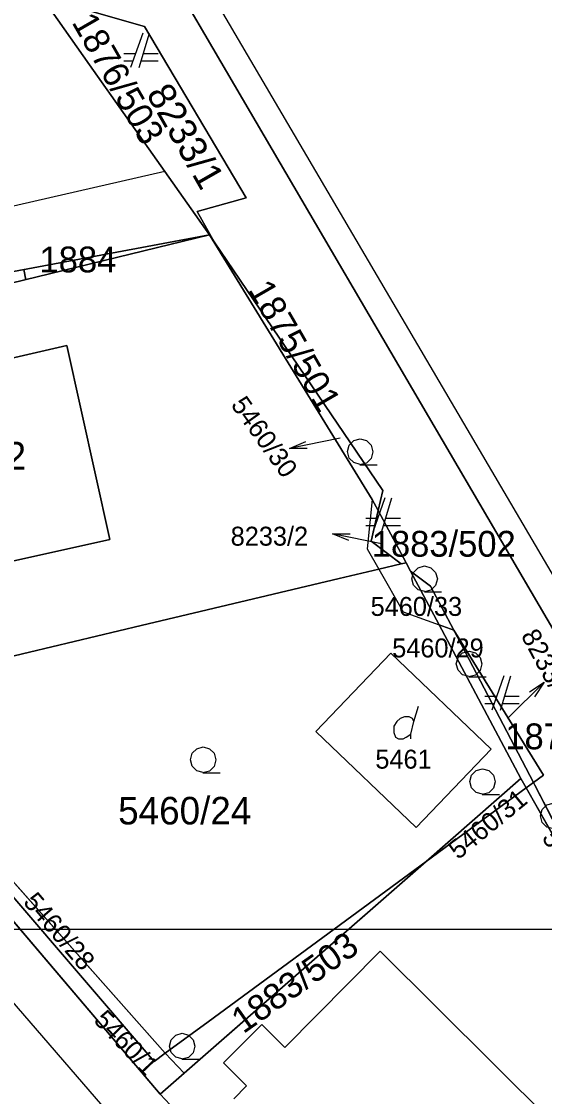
# Model space of a CAD drawing. Extents: x -263587 to -261993, y -1238795 to -1236748.
# Drawn here: x -262882.4 to -262852, y -1237097.8 to -1237035.4 of the extents above; entities that cross this region are included whole.
import ezdxf

# ---------------------------------------------------------------- set-up
doc = ezdxf.new("R2010")
doc.units = 0
for name, color, linetype in [('Vrstva 1', 7, 'Continuous'), ('Vrstva 3', 7, 'Continuous'), ('Vrstva 51', 7, 'Continuous')]:
    doc.layers.add(name, color=color, linetype=linetype)

msp = doc.modelspace()

# ---------------------------------------------------------------- linework, layer by layer
at = {"layer": 'Vrstva 1'}
for p, q in [((-262873.84, -1237029.6), (-262829.31, -1237105.43)), ((-262833.86, -1237100.89), (-262873.83, -1237032.62)), ((-262873.83, -1237032.62), (-262833.86, -1237100.89)), ((-262875.29, -1237035.67), (-262880.65, -1237034.14)), ((-262880.65, -1237034.14), (-262875.29, -1237035.67)), ((-262878.48, -1237037.88), (-262881.06, -1237034.23)), ((-262881.06, -1237034.23), (-262878.48, -1237037.88)), ((-262875.39, -1237036.05), (-262876.09, -1237038.05)), ((-262875.59, -1237038.05), (-262874.99, -1237036.05)), ((-262869.38, -1237045.62), (-262875.29, -1237035.67)), ((-262875.29, -1237035.67), (-262869.38, -1237045.62)), ((-262875.81, -1237037.25), (-262876.49, -1237037.25)), ((-262874.49, -1237037.25), (-262875.35, -1237037.25)), ((-262874.1, -1237044.08), (-262878.48, -1237037.88)), ((-262878.48, -1237037.88), (-262874.1, -1237044.08)), ((-262876.49, -1237037.65), (-262875.95, -1237037.65)), ((-262875.47, -1237037.65), (-262874.49, -1237037.65)), ((-262874.1, -1237044.08), (-262883.33, -1237046.2)), ((-262871.5, -1237047.76), (-262874.1, -1237044.08)), ((-262874.1, -1237044.08), (-262871.5, -1237047.76)), ((-262872.23, -1237046.4), (-262869.38, -1237045.62)), ((-262869.38, -1237045.62), (-262872.23, -1237046.4)), ((-262871.23, -1237048.16), (-262872.23, -1237046.4)), ((-262872.23, -1237046.4), (-262871.23, -1237048.16)), ((-262871.5, -1237047.76), (-262911.11, -1237057.42)), ((-262911.11, -1237057.42), (-262871.5, -1237047.76)), ((-262909.25, -1237054.82), (-262871.5, -1237047.76)), ((-262871.5, -1237047.76), (-262909.25, -1237054.82)), ((-262862.05, -1237063.12), (-262871.5, -1237047.76)), ((-262871.5, -1237047.76), (-262871.23, -1237048.16)), ((-262871.23, -1237048.16), (-262871.5, -1237047.76)), ((-262871.5, -1237047.76), (-262862.05, -1237063.12)), ((-262861.43, -1237062.6), (-262871.23, -1237048.16)), ((-262871.23, -1237048.16), (-262861.43, -1237062.6)), ((-262891.59, -1237056.9), (-262879.8, -1237054.19)), ((-262879.8, -1237054.19), (-262891.59, -1237056.9)), ((-262879.8, -1237054.19), (-262877.29, -1237065.45)), ((-262877.29, -1237065.45), (-262879.8, -1237054.19)), ((-262865.838, -1237060.161), (-262866.858, -1237060.168)), ((-262861.7, -1237063.77), (-262861.43, -1237062.6)), ((-262861.43, -1237062.6), (-262861.7, -1237063.77)), ((-262862.05, -1237063.12), (-262862.34, -1237066)), ((-262861.7, -1237063.77), (-262862.05, -1237063.12)), ((-262862.05, -1237063.12), (-262861.7, -1237063.77)), ((-262861.32, -1237063.03), (-262862.02, -1237065.03)), ((-262861.52, -1237065.03), (-262860.92, -1237063.03)), ((-262862.12, -1237065.55), (-262861.7, -1237063.77)), ((-262861.7, -1237063.77), (-262862.12, -1237065.55)), ((-262860.09, -1237066.8), (-262861.7, -1237063.77)), ((-262861.7, -1237063.77), (-262860.09, -1237066.8)), ((-262861.74, -1237064.23), (-262862.42, -1237064.23)), ((-262862.42, -1237064.63), (-262861.88, -1237064.63)), ((-262861.4, -1237064.63), (-262860.42, -1237064.63)), ((-262860.42, -1237064.23), (-262861.28, -1237064.23)), ((-262863.42, -1237065.519), (-262864.36, -1237065.125)), ((-262877.29, -1237065.45), (-262889.03, -1237068.06)), ((-262889.03, -1237068.06), (-262877.29, -1237065.45)), ((-262862.34, -1237066), (-262861.67, -1237067.17)), ((-262860.38, -1237066.87), (-262862.12, -1237065.55)), ((-262862.12, -1237065.55), (-262860.38, -1237066.87)), ((-262861.67, -1237067.17), (-262863.97, -1237067.72)), ((-262863.97, -1237067.72), (-262861.67, -1237067.17)), ((-262860.38, -1237066.87), (-262861.67, -1237067.17)), ((-262861.67, -1237067.17), (-262860.38, -1237066.87)), ((-262861.67, -1237067.17), (-262860.25, -1237069.65)), ((-262860.09, -1237066.8), (-262860.38, -1237066.87)), ((-262860.38, -1237066.87), (-262860.09, -1237066.8)), ((-262859.83, -1237067.29), (-262860.09, -1237066.8)), ((-262860.09, -1237066.8), (-262859.83, -1237067.29)), ((-262858.66, -1237068.17), (-262859.83, -1237067.29)), ((-262858.17, -1237070.41), (-262859.83, -1237067.29)), ((-262859.83, -1237067.29), (-262858.66, -1237068.17)), ((-262859.83, -1237067.29), (-262858.17, -1237070.41)), ((-262863.97, -1237067.72), (-262875.47, -1237070.45)), ((-262875.47, -1237070.45), (-262863.97, -1237067.72)), ((-262857.32, -1237070.72), (-262858.66, -1237068.17)), ((-262858.66, -1237068.17), (-262857.32, -1237070.72)), ((-262860.25, -1237069.65), (-262858.17, -1237070.41)), ((-262857.32, -1237070.72), (-262858.17, -1237070.41)), ((-262853.42, -1237079.33), (-262858.17, -1237070.41)), ((-262858.17, -1237070.41), (-262857.32, -1237070.72)), ((-262858.17, -1237070.41), (-262853.42, -1237079.33)), ((-262875.47, -1237070.45), (-262881.96, -1237071.99)), ((-262881.96, -1237071.99), (-262875.47, -1237070.45)), ((-262852.1, -1237079.13), (-262857.32, -1237070.72)), ((-262857.32, -1237070.72), (-262852.1, -1237079.13)), ((-262852.68, -1237079.56), (-262857.32, -1237070.72)), ((-262857.32, -1237070.72), (-262852.68, -1237079.56)), ((-262881.96, -1237071.99), (-262884.56, -1237072.61)), ((-262884.56, -1237072.61), (-262881.96, -1237071.99)), ((-262865.33, -1237076.6), (-262860.97, -1237072.05)), ((-262860.97, -1237072.05), (-262865.33, -1237076.6)), ((-262860.97, -1237072.05), (-262855.15, -1237077.63)), ((-262855.15, -1237077.63), (-262860.97, -1237072.05)), ((-262854.41, -1237073.37), (-262855.11, -1237075.37)), ((-262854.61, -1237075.37), (-262854.01, -1237073.37)), ((-262874.38, -1237097.67), (-262894.66, -1237073.8)), ((-262894.66, -1237073.8), (-262874.38, -1237097.67)), ((-262852.91, -1237074.3), (-262852.059, -1237073.739)), ((-262854.83, -1237074.57), (-262855.51, -1237074.57)), ((-262853.51, -1237074.57), (-262854.37, -1237074.57)), ((-262859.63, -1237076.03), (-262859.36, -1237075.13)), ((-262855.51, -1237074.97), (-262854.97, -1237074.97)), ((-262854.49, -1237074.97), (-262853.51, -1237074.97)), ((-262859.51, -1237082.18), (-262865.33, -1237076.6)), ((-262865.33, -1237076.6), (-262859.51, -1237082.18)), ((-262855.15, -1237077.63), (-262859.51, -1237082.18)), ((-262859.51, -1237082.18), (-262855.15, -1237077.63)), ((-262852.68, -1237079.56), (-262852.1, -1237079.13)), ((-262852.1, -1237079.13), (-262852.68, -1237079.56)), ((-262858.93, -1237084.15), (-262853.42, -1237079.33)), ((-262853.42, -1237079.33), (-262858.93, -1237084.15)), ((-262853.42, -1237079.33), (-262853.11, -1237079.87)), ((-262853.11, -1237079.87), (-262853.42, -1237079.33)), ((-262852.68, -1237079.56), (-262853.11, -1237079.87)), ((-262853.11, -1237079.87), (-262852.68, -1237079.56)), ((-262852.6, -1237079.72), (-262852.68, -1237079.56)), ((-262852.68, -1237079.56), (-262852.6, -1237079.72)), ((-262846.54, -1237091.48), (-262852.6, -1237079.72)), ((-262852.6, -1237079.72), (-262846.54, -1237091.48)), ((-262853.11, -1237079.87), (-262858.93, -1237084.15)), ((-262858.93, -1237084.15), (-262853.11, -1237079.87)), ((-262846.54, -1237091.48), (-262853.11, -1237079.87)), ((-262853.11, -1237079.87), (-262846.54, -1237091.48)), ((-262886.16, -1237081.67), (-262874.08, -1237095.28)), ((-262874.08, -1237095.28), (-262886.16, -1237081.67)), ((-262858.93, -1237084.15), (-262874.38, -1237097.67)), ((-262874.38, -1237097.67), (-262858.93, -1237084.15)), ((-262871.59, -1237093.46), (-262858.93, -1237084.15)), ((-262858.93, -1237084.15), (-262871.59, -1237093.46)), ((-262883.04, -1237086.04), (-262874.73, -1237095.76)), ((-262874.73, -1237095.76), (-262883.04, -1237086.04)), ((-262861.59, -1237089.36), (-262867.13, -1237094.95)), ((-262867.13, -1237094.95), (-262861.59, -1237089.36)), ((-262845.21, -1237105.62), (-262861.59, -1237089.36)), ((-262861.59, -1237089.36), (-262845.21, -1237105.62)), ((-262871.6, -1237105.38), (-262884.15, -1237090.92)), ((-262874.08, -1237095.28), (-262871.59, -1237093.46)), ((-262871.59, -1237093.46), (-262874.08, -1237095.28)), ((-262868.47, -1237093.61), (-262870.69, -1237095.84)), ((-262870.69, -1237095.84), (-262868.47, -1237093.61)), ((-262867.13, -1237094.95), (-262868.47, -1237093.61)), ((-262868.47, -1237093.61), (-262867.13, -1237094.95)), ((-262874.73, -1237095.76), (-262874.08, -1237095.28)), ((-262874.08, -1237095.28), (-262874.73, -1237095.76)), ((-262870.69, -1237095.84), (-262869.35, -1237097.18)), ((-262869.35, -1237097.18), (-262870.69, -1237095.84)), ((-262869.35, -1237097.18), (-262870.09, -1237097.93)), ((-262870.09, -1237097.93), (-262869.35, -1237097.18)), ((-262868.89, -1237103.44), (-262874.38, -1237097.67)), ((-262874.38, -1237097.67), (-262868.89, -1237103.44))]:
    msp.add_line(p, q, dxfattribs=at)
for points in [[(-262863.92, -1237059.56), (-262866.858, -1237060.168), (-262865.919, -1237059.77)], [(-262862.75, -1237061.09), (-262863.13, -1237060.99), (-262863.4, -1237060.72), (-262863.5, -1237060.35), (-262863.4, -1237059.98), (-262863.13, -1237059.71), (-262862.76, -1237059.61), (-262862.39, -1237059.71), (-262862.12, -1237059.98), (-262862.02, -1237060.36), (-262862.12, -1237060.74), (-262862.39, -1237061.01), (-262862.77, -1237061.11), (-262861.77, -1237061.11)], [(-262861.42, -1237065.72), (-262864.36, -1237065.125), (-262863.341, -1237065.127)], [(-262859, -1237068.47), (-262859.38, -1237068.37), (-262859.65, -1237068.1), (-262859.75, -1237067.73), (-262859.65, -1237067.36), (-262859.38, -1237067.09), (-262859.01, -1237066.99), (-262858.64, -1237067.09), (-262858.37, -1237067.36), (-262858.27, -1237067.74), (-262858.37, -1237068.12), (-262858.64, -1237068.39), (-262859.02, -1237068.49), (-262858.02, -1237068.49)], [(-262856.42, -1237073.41), (-262856.8, -1237073.31), (-262857.07, -1237073.04), (-262857.17, -1237072.67), (-262857.07, -1237072.3), (-262856.8, -1237072.03), (-262856.43, -1237071.93), (-262856.06, -1237072.03), (-262855.79, -1237072.3), (-262855.69, -1237072.68), (-262855.79, -1237073.06), (-262856.06, -1237073.33), (-262856.44, -1237073.43), (-262855.44, -1237073.43)], [(-262854.19, -1237075.85), (-262852.059, -1237073.739), (-262852.628, -1237074.585)], [(-262859.81, -1237077.02), (-262859.81, -1237076.75), (-262859.63, -1237076.03), (-262859.72, -1237075.85), (-262859.9, -1237075.76), (-262860.17, -1237075.76), (-262860.44, -1237075.85), (-262860.62, -1237076.03), (-262860.8, -1237076.3), (-262860.8, -1237076.66), (-262860.71, -1237076.93), (-262860.53, -1237077.02), (-262860.26, -1237077.02), (-262860.08, -1237076.93), (-262859.81, -1237076.75)], [(-262871.87, -1237078.98), (-262872.25, -1237078.88), (-262872.52, -1237078.61), (-262872.62, -1237078.24), (-262872.52, -1237077.87), (-262872.25, -1237077.6), (-262871.88, -1237077.5), (-262871.51, -1237077.6), (-262871.24, -1237077.87), (-262871.14, -1237078.25), (-262871.24, -1237078.63), (-262871.51, -1237078.9), (-262871.89, -1237079), (-262870.89, -1237079)], [(-262855.64, -1237080.25), (-262856.02, -1237080.15), (-262856.29, -1237079.88), (-262856.39, -1237079.51), (-262856.29, -1237079.14), (-262856.02, -1237078.87), (-262855.65, -1237078.77), (-262855.28, -1237078.87), (-262855.01, -1237079.14), (-262854.91, -1237079.52), (-262855.01, -1237079.9), (-262855.28, -1237080.17), (-262855.66, -1237080.27), (-262854.66, -1237080.27)], [(-262851.53, -1237082.25), (-262851.91, -1237082.15), (-262852.18, -1237081.88), (-262852.28, -1237081.51), (-262852.18, -1237081.14), (-262851.91, -1237080.87), (-262851.54, -1237080.77), (-262851.17, -1237080.87), (-262850.9, -1237081.14), (-262850.8, -1237081.52), (-262850.9, -1237081.9), (-262851.17, -1237082.17), (-262851.55, -1237082.27), (-262850.55, -1237082.27)], [(-262873.09, -1237095.61), (-262873.47, -1237095.51), (-262873.74, -1237095.24), (-262873.84, -1237094.87), (-262873.74, -1237094.5), (-262873.47, -1237094.23), (-262873.1, -1237094.13), (-262872.73, -1237094.23), (-262872.46, -1237094.5), (-262872.36, -1237094.88), (-262872.46, -1237095.26), (-262872.73, -1237095.53), (-262873.11, -1237095.63), (-262872.11, -1237095.63)]]:
    msp.add_lwpolyline(points, dxfattribs=at)
at = {"layer": 'Vrstva 3'}
for points in [[(-262871.463, -1237047.751), (-262871.5, -1237047.76), (-262874.098, -1237044.082), (-262878.476, -1237037.885), (-262881.06, -1237034.23), (-262880.65, -1237034.14), (-262875.29, -1237035.67), (-262869.38, -1237045.62), (-262872.23, -1237046.4)], [(-262882.181, -1237050.365), (-262882.29, -1237049.778), (-262871.5, -1237047.76)], [(-262871.5, -1237047.76), (-262871.463, -1237047.751), (-262871.23, -1237048.16), (-262861.43, -1237062.6), (-262861.7, -1237063.77), (-262862.05, -1237063.12)], [(-262882.29, -1237049.778), (-262882.181, -1237050.365), (-262911.11, -1237057.42), (-262909.25, -1237054.82)], [(-262874.08, -1237095.28), (-262872.983, -1237096.447), (-262874.38, -1237097.67), (-262894.66, -1237073.8), (-262905.49, -1237065.24), (-262914.37, -1237058.22), (-262911.11, -1237057.42), (-262911.5, -1237058.55), (-262911.05, -1237060.14), (-262910.06, -1237061.47), (-262906.86, -1237063.74), (-262895.31, -1237071.36), (-262887.04, -1237080.68), (-262886.16, -1237081.67)], [(-262862.12, -1237065.55), (-262861.7, -1237063.77), (-262860.09, -1237066.8), (-262860.38, -1237066.87)], [(-262852.68, -1237079.56), (-262852.1, -1237079.13), (-262857.32, -1237070.72), (-262858.66, -1237068.17), (-262859.83, -1237067.29), (-262858.17, -1237070.41), (-262853.42, -1237079.33), (-262853.11, -1237079.87), (-262846.54, -1237091.48), (-262852.6, -1237079.72)], [(-262852.1, -1237079.13), (-262852.68, -1237079.56), (-262852.6, -1237079.72), (-262846.54, -1237091.48), (-262853.11, -1237079.87), (-262853.42, -1237079.33), (-262858.17, -1237070.41), (-262859.83, -1237067.29), (-262858.66, -1237068.17), (-262857.32, -1237070.72)], [(-262872.983, -1237096.447), (-262874.08, -1237095.28), (-262871.59, -1237093.46), (-262858.93, -1237084.15)]]:
    msp.add_lwpolyline(points, close=True, dxfattribs=at)
at = {"layer": 'Vrstva 51'}
msp.add_lwpolyline([(-262992.03, -1237088.09), (-262695.03, -1237088.09), (-262695.03, -1238768.09), (-262992.03, -1238768.09)], close=True, dxfattribs=at)

# ---------------------------------------------------------------- texts
at = {"layer": 'Vrstva 1'}
for s, height, rotation, p in [('8233/1', 1.6, 299.71422, (-262875.215, -1237039.575)), ('5460/30', 1.1, 305.4438, (-262870.305, -1237057.64)), ('8233/3', 1.1, 298.22453, (-262853.437, -1237071.029)), ('5460/31', 1.1, 39.3622, (-262857.06, -1237084.084)), ('5460/32', 1.1, 298.33913, (-262852.222, -1237082.74)), ('5460/28', 1.1, 310.65772, (-262882.379, -1237086.538)), ('5460/1', 1.1, 313.6371, (-262878.292, -1237093.42))]:
    msp.add_text(s, height=height, rotation=rotation, dxfattribs=at).set_placement(p)
for s, height, p in [('5462', 1.6, (-262886.922, -1237061.39)), ('8233/2', 1.1, (-262870.278, -1237065.81)), ('5460/33', 1.1, (-262862.149, -1237069.89)), ('5460/29', 1.1, (-262860.894, -1237072.3)), ('5461', 1.1, (-262861.873, -1237078.76)), ('5460/24', 1.6, (-262876.814, -1237082))]:
    msp.add_text(s, height=height, dxfattribs=at).set_placement(p)
at = {"layer": 'Vrstva 3'}
for s, rotation, p in [('1876/503', 299.88611, (-262879.541, -1237035.414)), ('1875/501', 300.0007, (-262869.291, -1237050.937)), ('1883/503', 35.2942, (-262869.543, -1237094.192))]:
    msp.add_text(s, height=1.5, rotation=rotation, dxfattribs=at).set_placement(p)
for s, p in [('1884', (-262881.384, -1237049.94)), ('1883/502', (-262862.081, -1237066.451)), ('1875/502', (-262854.322, -1237077.636))]:
    msp.add_text(s, height=1.5, dxfattribs=at).set_placement(p)

doc.saveas('drawing.dxf')
